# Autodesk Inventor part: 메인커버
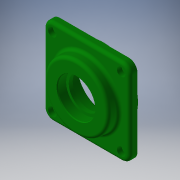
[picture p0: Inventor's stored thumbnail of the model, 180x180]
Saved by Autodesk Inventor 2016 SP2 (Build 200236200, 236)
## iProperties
Created: 2018-09
Part Number: 메인커버
Material: 알루미늄 6061
Document SubType Name: Modeling
Designer: mduedu
Density: 2.71 g/cm^3
Mass: 178.463 g
Surface Area: 197.883 cm^2
Volume: 65.8536 cm^3
Appearance: 진녹색
Author: mduedu
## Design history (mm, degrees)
sketch "스케치1"
  geometry: L1 (-40, -40)-(40, -40); L2 (40, -40)-(40, 40); L3 (40, 40)-(-40, 40); L4 (-40, 40)-(-40, -40); L5 (-40, -40)-(40, 40); L6 (40, -40)-(-40, 40); 1 further point
  constraints: 12 end point, 2 midpoint, 2 parallel, 1 horizontal, 1 perpendicular
  dimensions: "d0" = 80 distance of L3.end L2.end; "d1" = 80 distance of L2.end L1.end
extrude "돌출1" new body sketch "스케치1" distance "d2" = 7; taper "d3" = 0 deg
sketch "스케치2"
  geometry: C1 r 30 at (0, 0); 1 further point
  constraints: 1 centre point, 1 coincident
  dimensions: "d4" = 60 diameter of C1
extrude "돌출2" join sketch "스케치2" distance "d5" = 10; taper "d6" = 0 deg
sketch "스케치3"
  geometry: C1 r 32.5 at (0, 0); 1 further point
  constraints: 1 centre point, 1 coincident
  dimensions: "d7" = 65 diameter of C1
extrude "돌출3" join sketch "스케치3" distance "d8" = 9; taper "d9" = 0 deg
sketch "스케치4"
  geometry: L1 (-32.5, -9)-(32.5, -9) reference; L2 (30, 17)-(-30, 17) reference; L3 (0, 17)-(0, -9); L4 (0, -9)-(23.5, -9); L5 (23.5, -9)-(23.5, 5); L6 (23.5, 5)-(0, 5); L7 (0, 5)-(0, -9); L8 (0, 5)-(15, 5); L9 (15, 5)-(15, 8.7); L10 (15, 8.7)-(0, 8.7); L11 (0, 8.7)-(0, 5); L12 (0, 8.7)-(17.5, 8.7); L13 (17.5, 8.7)-(17.5, 17); L14 (17.5, 17)-(0, 17); L15 (0, 17)-(0, 8.7); 1 further point
  constraints: 26 end point, 6 parallel, 3 horizontal, 3 perpendicular, 2 midpoint, 1 point on line
  dimensions: "d10" = 14 distance of L4.end L5.end; "d12" = 8.3 distance of L12.end L13.end; "d13" = 35 diameter of L13 L3; "d14" = 30 diameter of L9 L3; "d15" = 47 diameter of L5 L3
revolve "회전1" sketch "스케치4" stored, may be unused: angle "d16" = 90 deg
fillet "모깎기1" dims "d17" = 8
fillet "모깎기2" dims "d18" = 3
fillet "모깎기3" dims "d19" = 3
chamfer "모따기1" distance "d20" = 0.8; stored, may be unused: second distance "d21" = 2, angle "d22" = 30 deg
chamfer "모따기2" distance "d23" = 1; stored, may be unused: second distance "d24" = 2, angle "d25" = 30 deg
fillet "모깎기4" dims "d26" = 0.3
sketch "스케치5"
  geometry: A1 r 8 centre (-32, 32) between (-32, 40) and (-40, 32) reference; A2 r 8 centre (-32, -32) between (-40, -32) and (-32, -40) reference; A3 r 8 centre (32, -32) between (32, -40) and (40, -32) reference; A4 r 8 centre (32, 32) between (40, 32) and (32, 40) reference; 5 further points
  constraints: 4 coincident
hole "구멍1" sketch "스케치5" at (-32, 32), (32, 32), (32, -32), (-32, -32) diameter "d27" = 4.5; stored, may be unused: countersink angle "d31" = 90 deg, drill point angle "d33" = 118 deg; dims "d28" = 6, "d29" = 8, "d30" = 4.4, "d32" = 8
node "솔리드1"
